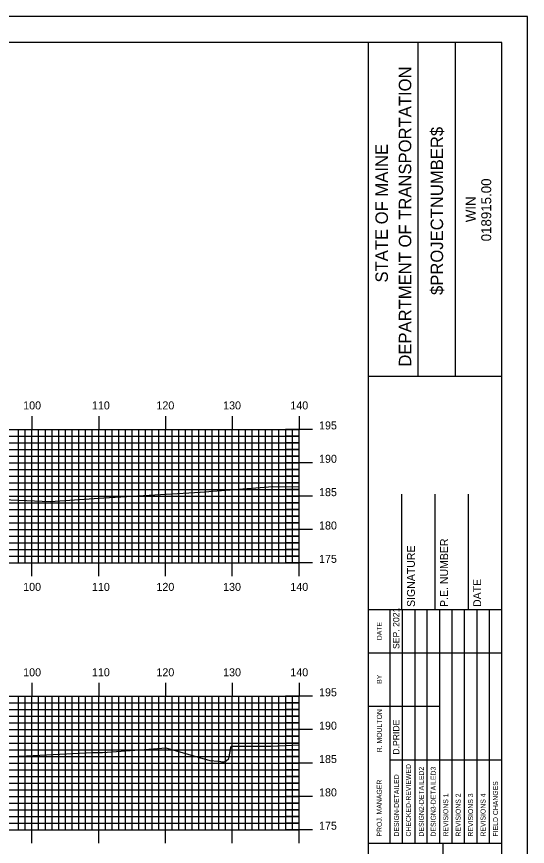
# Model space of a CAD drawing. Extents: x 1823179 to 1823522, y 442591 to 442811.
# Drawn here: x 1823442.5 to 1823519, y 442686.2 to 442810.5 of the extents above; entities that cross this region are included whole.
import ezdxf

# ---------------------------------------------------------------- set-up
doc = ezdxf.new("R2010")
doc.units = 0
for name, color, linetype in [('BORDER', 7, 'Continuous'), ('H_V ANNOTATION', 7, 'Continuous'), ('MAJOR', 7, 'Continuous'), ('MINOR', 7, 'Continuous'), ('PLOT BOUNDARY', 7, 'Continuous'), ('S_Roadway_Centerline', 7, 'Continuous')]:
    doc.layers.add(name, color=color, linetype=linetype)

msp = doc.modelspace()

# ---------------------------------------------------------------- linework, layer by layer
at = {"layer": 'BORDER'}
for p, q in [((1823495.2, 442596.67), (1823495.2, 442806.67)), ((1823502.65, 442756.66), (1823502.65, 442806.66)), ((1823508.24, 442756.66), (1823508.24, 442806.66)), ((1823495.2, 442756.65), (1823515.2, 442756.65)), ((1823500.2, 442721.67), (1823500.2, 442738.97)), ((1823505.2, 442721.67), (1823505.2, 442738.97)), ((1823510.2, 442721.67), (1823510.2, 442738.97)), ((1823495.2, 442721.67), (1823515.2, 442721.67)), ((1823495.2, 442686.67), (1823515.2, 442686.67)), ((1823506.38, 442616.67), (1823506.38, 442686.67))]:
    msp.add_line(p, q, dxfattribs=at)
msp.add_lwpolyline([(1823195.2, 442596.67), (1823515.2, 442596.67), (1823515.2, 442806.67), (1823195.2, 442806.67)], close=True, dxfattribs=at)
for points in [[(1823498.43, 442715.17), (1823498.43, 442721.67)], [(1823500.29, 442686.68), (1823500.29, 442721.67)], [(1823502.15, 442721.67), (1823502.15, 442686.68)], [(1823504.02, 442686.68), (1823504.02, 442721.67)], [(1823505.88, 442686.68), (1823505.88, 442721.67)], [(1823507.74, 442686.68), (1823507.74, 442721.67)], [(1823509.61, 442686.68), (1823509.61, 442721.67)], [(1823511.47, 442686.68), (1823511.47, 442721.67)], [(1823513.33, 442686.68), (1823513.33, 442721.67)], [(1823498.43, 442686.68), (1823498.43, 442720.26)], [(1823495.2, 442715.17), (1823515.2, 442715.17)], [(1823495.2, 442707.17), (1823498.43, 442707.17)], [(1823498.43, 442707.17), (1823505.88, 442707.17)], [(1823498.43, 442699.17), (1823515.2, 442699.17)]]:
    msp.add_lwpolyline(points, dxfattribs=at)
at = {"layer": 'MAJOR'}
for p, q in [((1823444.8, 442750.67), (1823444.8, 442748.67)), ((1823454.8, 442750.67), (1823454.8, 442748.67)), ((1823464.8, 442750.67), (1823464.8, 442748.67)), ((1823474.8, 442750.67), (1823474.8, 442748.67)), ((1823484.8, 442750.67), (1823484.8, 442748.67)), ((1823204.8, 442748.67), (1823484.8, 442748.67)), ((1823204.8, 442748.67), (1823484.8, 442748.67)), ((1823444.8, 442728.67), (1823444.8, 442748.67)), ((1823454.8, 442728.67), (1823454.8, 442748.67)), ((1823464.8, 442728.67), (1823464.8, 442748.67)), ((1823474.8, 442728.67), (1823474.8, 442748.67)), ((1823486.8, 442748.67), (1823482.79, 442748.67)), ((1823484.8, 442728.67), (1823484.8, 442748.67)), ((1823484.8, 442728.67), (1823484.8, 442748.67)), ((1823204.8, 442743.67), (1823484.8, 442743.67)), ((1823486.8, 442743.67), (1823482.79, 442743.67)), ((1823204.8, 442738.67), (1823484.8, 442738.67)), ((1823486.8, 442738.67), (1823482.79, 442738.67)), ((1823204.8, 442733.67), (1823484.8, 442733.67)), ((1823486.8, 442733.67), (1823482.79, 442733.67)), ((1823204.8, 442728.67), (1823484.8, 442728.67)), ((1823204.8, 442728.67), (1823484.8, 442728.67)), ((1823444.8, 442726.66), (1823444.8, 442728.67)), ((1823454.8, 442726.66), (1823454.8, 442728.67)), ((1823464.8, 442726.66), (1823464.8, 442728.67)), ((1823474.8, 442726.66), (1823474.8, 442728.67)), ((1823486.8, 442728.67), (1823482.79, 442728.67)), ((1823484.8, 442726.66), (1823484.8, 442728.67)), ((1823444.8, 442710.67), (1823444.8, 442708.67)), ((1823454.8, 442710.67), (1823454.8, 442708.67)), ((1823464.8, 442710.67), (1823464.8, 442708.67)), ((1823474.8, 442710.67), (1823474.8, 442708.67)), ((1823484.8, 442710.67), (1823484.8, 442708.67)), ((1823344.8, 442708.67), (1823484.8, 442708.67)), ((1823344.8, 442708.67), (1823484.8, 442708.67)), ((1823444.8, 442688.67), (1823444.8, 442708.67)), ((1823454.8, 442688.67), (1823454.8, 442708.67)), ((1823464.8, 442688.67), (1823464.8, 442708.67)), ((1823474.8, 442688.67), (1823474.8, 442708.67)), ((1823486.8, 442708.67), (1823482.79, 442708.67)), ((1823484.8, 442688.67), (1823484.8, 442708.67)), ((1823484.8, 442688.67), (1823484.8, 442708.67)), ((1823344.8, 442703.67), (1823484.8, 442703.67)), ((1823486.8, 442703.67), (1823482.79, 442703.67)), ((1823344.8, 442698.67), (1823484.8, 442698.67)), ((1823486.8, 442698.67), (1823482.79, 442698.67)), ((1823344.8, 442693.67), (1823484.8, 442693.67)), ((1823486.8, 442693.67), (1823482.79, 442693.67)), ((1823344.8, 442688.67), (1823484.8, 442688.67)), ((1823344.8, 442688.67), (1823484.8, 442688.67)), ((1823444.8, 442686.66), (1823444.8, 442688.67)), ((1823454.8, 442686.66), (1823454.8, 442688.67)), ((1823464.8, 442686.66), (1823464.8, 442688.67)), ((1823474.8, 442686.66), (1823474.8, 442688.67)), ((1823486.8, 442688.67), (1823482.79, 442688.67)), ((1823484.8, 442686.66), (1823484.8, 442688.67))]:
    msp.add_line(p, q, dxfattribs=at)
at = {"layer": 'MINOR'}
for p, q in [((1823442.8, 442728.67), (1823442.8, 442748.67)), ((1823443.8, 442728.67), (1823443.8, 442748.67)), ((1823445.8, 442728.67), (1823445.8, 442748.67)), ((1823446.8, 442728.67), (1823446.8, 442748.67)), ((1823447.8, 442728.67), (1823447.8, 442748.67)), ((1823448.8, 442728.67), (1823448.8, 442748.67)), ((1823449.8, 442728.67), (1823449.8, 442748.67)), ((1823450.8, 442728.67), (1823450.8, 442748.67)), ((1823451.8, 442728.67), (1823451.8, 442748.67)), ((1823452.8, 442728.67), (1823452.8, 442748.67)), ((1823453.8, 442728.67), (1823453.8, 442748.67)), ((1823455.8, 442728.67), (1823455.8, 442748.67)), ((1823456.8, 442728.67), (1823456.8, 442748.67)), ((1823457.8, 442728.67), (1823457.8, 442748.67)), ((1823458.8, 442728.67), (1823458.8, 442748.67)), ((1823459.8, 442728.67), (1823459.8, 442748.67)), ((1823460.8, 442728.67), (1823460.8, 442748.67)), ((1823461.8, 442728.67), (1823461.8, 442748.67)), ((1823462.8, 442728.67), (1823462.8, 442748.67)), ((1823463.8, 442728.67), (1823463.8, 442748.67)), ((1823465.8, 442728.67), (1823465.8, 442748.67)), ((1823466.8, 442728.67), (1823466.8, 442748.67)), ((1823467.8, 442728.67), (1823467.8, 442748.67)), ((1823468.8, 442728.67), (1823468.8, 442748.67)), ((1823469.8, 442728.67), (1823469.8, 442748.67)), ((1823470.8, 442728.67), (1823470.8, 442748.67)), ((1823471.8, 442728.67), (1823471.8, 442748.67)), ((1823472.8, 442728.67), (1823472.8, 442748.67)), ((1823473.8, 442728.67), (1823473.8, 442748.67)), ((1823475.8, 442728.67), (1823475.8, 442748.67)), ((1823476.8, 442728.67), (1823476.8, 442748.67)), ((1823477.8, 442728.67), (1823477.8, 442748.67)), ((1823478.8, 442728.67), (1823478.8, 442748.67)), ((1823479.8, 442728.67), (1823479.8, 442748.67)), ((1823480.8, 442728.67), (1823480.8, 442748.67)), ((1823481.8, 442728.67), (1823481.8, 442748.67)), ((1823482.8, 442728.67), (1823482.8, 442748.67)), ((1823483.8, 442728.67), (1823483.8, 442748.67)), ((1823204.8, 442747.67), (1823484.8, 442747.67)), ((1823484.8, 442747.67), (1823482.79, 442747.67)), ((1823204.8, 442746.67), (1823484.8, 442746.67)), ((1823204.8, 442745.67), (1823484.8, 442745.67)), ((1823484.8, 442746.67), (1823482.79, 442746.67)), ((1823484.8, 442745.67), (1823482.79, 442745.67)), ((1823204.8, 442744.67), (1823484.8, 442744.67)), ((1823484.8, 442744.67), (1823482.79, 442744.67)), ((1823204.8, 442742.67), (1823484.8, 442742.67)), ((1823484.8, 442742.67), (1823482.79, 442742.67)), ((1823204.8, 442741.67), (1823484.8, 442741.67)), ((1823204.8, 442740.67), (1823484.8, 442740.67)), ((1823484.8, 442741.67), (1823482.79, 442741.67)), ((1823484.8, 442740.67), (1823482.79, 442740.67)), ((1823204.8, 442739.67), (1823484.8, 442739.67)), ((1823484.8, 442739.67), (1823482.79, 442739.67)), ((1823204.8, 442737.67), (1823484.8, 442737.67)), ((1823484.8, 442737.67), (1823482.79, 442737.67)), ((1823204.8, 442736.67), (1823484.8, 442736.67)), ((1823204.8, 442735.67), (1823484.8, 442735.67)), ((1823484.8, 442736.67), (1823482.79, 442736.67)), ((1823484.8, 442735.67), (1823482.79, 442735.67)), ((1823204.8, 442734.67), (1823484.8, 442734.67)), ((1823484.8, 442734.67), (1823482.79, 442734.67)), ((1823204.8, 442732.67), (1823484.8, 442732.67)), ((1823484.8, 442732.67), (1823482.79, 442732.67)), ((1823204.8, 442731.67), (1823484.8, 442731.67)), ((1823204.8, 442730.67), (1823484.8, 442730.67)), ((1823484.8, 442731.67), (1823482.79, 442731.67)), ((1823484.8, 442730.67), (1823482.79, 442730.67)), ((1823204.8, 442729.67), (1823484.8, 442729.67)), ((1823484.8, 442729.67), (1823482.79, 442729.67)), ((1823442.8, 442688.67), (1823442.8, 442708.67)), ((1823443.8, 442688.67), (1823443.8, 442708.67)), ((1823445.8, 442688.67), (1823445.8, 442708.67)), ((1823446.8, 442688.67), (1823446.8, 442708.67)), ((1823447.8, 442688.67), (1823447.8, 442708.67)), ((1823448.8, 442688.67), (1823448.8, 442708.67)), ((1823449.8, 442688.67), (1823449.8, 442708.67)), ((1823450.8, 442688.67), (1823450.8, 442708.67)), ((1823451.8, 442688.67), (1823451.8, 442708.67)), ((1823452.8, 442688.67), (1823452.8, 442708.67)), ((1823453.8, 442688.67), (1823453.8, 442708.67)), ((1823455.8, 442688.67), (1823455.8, 442708.67)), ((1823456.8, 442688.67), (1823456.8, 442708.67)), ((1823457.8, 442688.67), (1823457.8, 442708.67)), ((1823458.8, 442688.67), (1823458.8, 442708.67)), ((1823459.8, 442688.67), (1823459.8, 442708.67)), ((1823460.8, 442688.67), (1823460.8, 442708.67)), ((1823461.8, 442688.67), (1823461.8, 442708.67)), ((1823462.8, 442688.67), (1823462.8, 442708.67)), ((1823463.8, 442688.67), (1823463.8, 442708.67)), ((1823465.8, 442688.67), (1823465.8, 442708.67)), ((1823466.8, 442688.67), (1823466.8, 442708.67)), ((1823467.8, 442688.67), (1823467.8, 442708.67)), ((1823468.8, 442688.67), (1823468.8, 442708.67)), ((1823469.8, 442688.67), (1823469.8, 442708.67)), ((1823470.8, 442688.67), (1823470.8, 442708.67)), ((1823471.8, 442688.67), (1823471.8, 442708.67)), ((1823472.8, 442688.67), (1823472.8, 442708.67)), ((1823473.8, 442688.67), (1823473.8, 442708.67)), ((1823475.8, 442688.67), (1823475.8, 442708.67)), ((1823476.8, 442688.67), (1823476.8, 442708.67)), ((1823477.8, 442688.67), (1823477.8, 442708.67)), ((1823478.8, 442688.67), (1823478.8, 442708.67)), ((1823479.8, 442688.67), (1823479.8, 442708.67)), ((1823480.8, 442688.67), (1823480.8, 442708.67)), ((1823481.8, 442688.67), (1823481.8, 442708.67)), ((1823482.8, 442688.67), (1823482.8, 442708.67)), ((1823483.8, 442688.67), (1823483.8, 442708.67)), ((1823344.8, 442707.67), (1823484.8, 442707.67)), ((1823484.8, 442707.67), (1823482.79, 442707.67)), ((1823344.8, 442706.67), (1823484.8, 442706.67)), ((1823484.8, 442706.67), (1823482.79, 442706.67)), ((1823344.8, 442705.67), (1823484.8, 442705.67)), ((1823344.8, 442704.67), (1823484.8, 442704.67)), ((1823484.8, 442705.67), (1823482.79, 442705.67)), ((1823484.8, 442704.67), (1823482.79, 442704.67)), ((1823344.8, 442702.67), (1823484.8, 442702.67)), ((1823484.8, 442702.67), (1823482.79, 442702.67)), ((1823344.8, 442701.67), (1823484.8, 442701.67)), ((1823484.8, 442701.67), (1823482.79, 442701.67)), ((1823344.8, 442700.67), (1823484.8, 442700.67)), ((1823344.8, 442699.67), (1823484.8, 442699.67)), ((1823484.8, 442700.67), (1823482.79, 442700.67)), ((1823484.8, 442699.67), (1823482.79, 442699.67)), ((1823344.8, 442697.67), (1823484.8, 442697.67)), ((1823484.8, 442697.67), (1823482.79, 442697.67)), ((1823344.8, 442696.67), (1823484.8, 442696.67)), ((1823484.8, 442696.67), (1823482.79, 442696.67)), ((1823344.8, 442695.67), (1823484.8, 442695.67)), ((1823344.8, 442694.67), (1823484.8, 442694.67)), ((1823484.8, 442695.67), (1823482.79, 442695.67)), ((1823484.8, 442694.67), (1823482.79, 442694.67)), ((1823344.8, 442692.67), (1823484.8, 442692.67)), ((1823484.8, 442692.67), (1823482.79, 442692.67)), ((1823344.8, 442691.67), (1823484.8, 442691.67)), ((1823484.8, 442691.67), (1823482.79, 442691.67)), ((1823344.8, 442690.67), (1823484.8, 442690.67)), ((1823344.8, 442689.67), (1823484.8, 442689.67)), ((1823484.8, 442690.67), (1823482.79, 442690.67)), ((1823484.8, 442689.67), (1823482.79, 442689.67))]:
    msp.add_line(p, q, dxfattribs=at)
at = {"layer": 'PLOT BOUNDARY'}
msp.add_lwpolyline([(1823179.01, 442590.55), (1823519.01, 442590.55), (1823519.01, 442810.55), (1823179.01, 442810.55)], close=True, dxfattribs=at)
at = {"layer": 'S_Roadway_Centerline'}
for points in [[(1823434.48, 442738.44), (1823447.5, 442737.89), (1823455.55, 442738.4), (1823469.99, 442739.27), (1823480.9, 442740.11), (1823484.8, 442740.05)], [(1823433.66, 442699.28), (1823443.96, 442699.75), (1823446.96, 442699.89), (1823453.9, 442700.27), (1823455.35, 442700.27), (1823462.99, 442700.82), (1823464.85, 442700.93), (1823471.45, 442699.04), (1823472.7, 442698.95), (1823473.02, 442698.9), (1823473.21, 442698.86), (1823473.3, 442698.84), (1823473.43, 442698.83), (1823473.47, 442698.83), (1823473.47, 442698.76), (1823473.48, 442698.81), (1823473.48, 442698.75), (1823473.48, 442698.81), (1823473.49, 442698.76), (1823473.52, 442698.83), (1823473.8, 442698.95), (1823473.9, 442699.02), (1823474.29, 442699.35), (1823474.63, 442701.19), (1823480.6, 442701.22), (1823484.8, 442701.39)]]:
    msp.add_lwpolyline(points, dxfattribs=at)

# ---------------------------------------------------------------- texts
at = {"layer": 'BORDER'}
for s, height, p in [('DEPARTMENT OF TRANSPORTATION', 1.8635, (1823501.61, 442758.08)), ('$PROJECTNUMBER$', 1.8635, (1823506.38, 442768.82)), ('STATE OF MAINE', 1.8635, (1823498.11, 442770.69)), ('018915.00', 1.491, (1823513.59, 442776.86)), ('WIN', 1.491, (1823511.27, 442779.73)), ('P.E. NUMBER', 1.1811, (1823507.12, 442722.06)), ('SIGNATURE', 1.181, (1823502.16, 442722.06)), ('DATE', 1.181, (1823512.08, 442722.06)), ('SEP. 2021', 0.969, (1823499.84, 442715.76)), ('DATE', 0.743, (1823497.2, 442717.08)), ('BY', 0.743, (1823497.2, 442710.54)), ('R. MOULTON', 0.745, (1823497.21, 442700.28)), ('D.PRIDE', 0.969, (1823499.84, 442699.92)), ('CHECKED-REVIEWED', 0.7455, (1823501.56, 442687.65)), ('DESIGN2-DETAILED2', 0.7455, (1823503.5, 442687.65)), ('DESIGN3-DETAILED3', 0.7455, (1823505.28, 442687.65)), ('PROJ. MANAGER', 0.7455, (1823497.2, 442687.65)), ('DESIGN-DETAILED', 0.7455, (1823499.77, 442687.65)), ('FIELD CHANGES', 0.7455, (1823514.6, 442687.65)), ('REVISIONS 1', 0.7455, (1823507.15, 442687.65)), ('REVISIONS 2', 0.7455, (1823509.01, 442687.65)), ('REVISIONS 3', 0.7455, (1823510.87, 442687.65)), ('REVISIONS 4', 0.7455, (1823512.74, 442687.65))]:
    msp.add_text(s, height=height, rotation=90, dxfattribs=at).set_placement(p)
at = {"layer": 'H_V ANNOTATION'}
for s, p in [('100', (1823443.48, 442751.67)), ('110', (1823453.78, 442751.67)), ('120', (1823463.44, 442751.67)), ('130', (1823473.43, 442751.67)), ('140', (1823483.5, 442751.67)), ('195', (1823487.8, 442748.67)), ('190', (1823487.8, 442743.67)), ('185', (1823487.8, 442738.67)), ('180', (1823487.8, 442733.67)), ('175', (1823487.8, 442728.67)), ('100', (1823443.48, 442724.47)), ('110', (1823453.78, 442724.47)), ('120', (1823463.44, 442724.47)), ('130', (1823473.43, 442724.47)), ('140', (1823483.5, 442724.47)), ('100', (1823443.48, 442711.67)), ('110', (1823453.78, 442711.67)), ('120', (1823463.44, 442711.67)), ('130', (1823473.43, 442711.67)), ('140', (1823483.5, 442711.67)), ('195', (1823487.8, 442708.67)), ('190', (1823487.8, 442703.67)), ('185', (1823487.8, 442698.67)), ('180', (1823487.8, 442693.67)), ('175', (1823487.8, 442688.67))]:
    msp.add_text(s, height=1.2, dxfattribs=at).set_placement(p)

doc.saveas('drawing.dxf')
